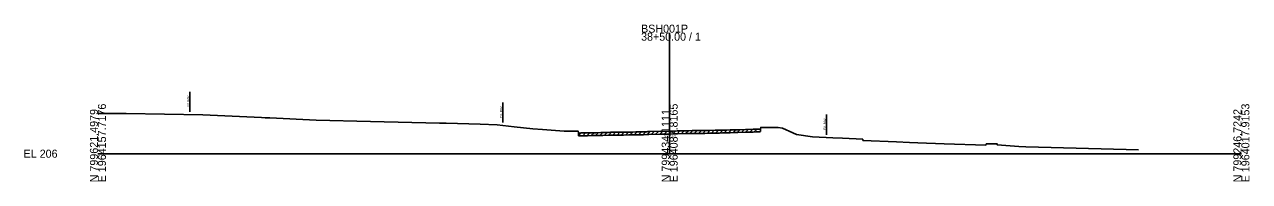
# Model space of a CAD drawing. Extents: x -26 to 1403, y -10 to 19587.
# Drawn here: x 974.3 to 1402.8, y 2490.3 to 2545.1 of the extents above; entities that cross this region are included whole.
import ezdxf

# ---------------------------------------------------------------- set-up
doc = ezdxf.new("R2010")
doc.units = 0
for name, color, linetype in [('Default', 7, 'Continuous'), ('RD_GPK_XS_Cell', 7, 'Continuous'), ('RD_XS_ExGround', 7, 'Continuous'), ('RD_XS_ExPaveRet', 7, 'Continuous'), ('RD_XS_ExRW', 7, 'Continuous'), ('RD_XS_TX_Elev_EX', 7, 'Continuous')]:
    doc.layers.add(name, color=color, linetype=linetype)

msp = doc.modelspace()

# ---------------------------------------------------------------- linework, layer by layer
at = {"layer": 'RD_GPK_XS_Cell'}
for p, q in [((1200, 2500), (1200, 2542.26)), ((1000, 2500), (1200, 2500)), ((1200, 2500), (1400, 2500))]:
    msp.add_line(p, q, dxfattribs=at)
at = {"layer": 'RD_XS_ExGround'}
msp.add_lwpolyline([(1000, 2514.09), (1009.85, 2513.98), (1036.73, 2513.55), (1057.27, 2512.59), (1058.5, 2512.54), (1060.15, 2512.47), (1076.38, 2511.69), (1095.34, 2511.2), (1119.51, 2510.7), (1121.79, 2510.64), (1133.7, 2510.27), (1139.68, 2510.06), (1145.66, 2509.4), (1152.08, 2508.65), (1155.46, 2508.44), (1163.14, 2507.88), (1166.11, 2507.88), (1167.98, 2507.87), (1168.08, 2507.27), (1168.12, 2507.19), (1168.94, 2507.24), (1169.69, 2507.25), (1170.57, 2507.26), (1171.29, 2507.28), (1173.23, 2507.31), (1174.12, 2507.33), (1175.89, 2507.38), (1176.57, 2507.4), (1178.56, 2507.45), (1179.29, 2507.47), (1180.89, 2507.51), (1181.29, 2507.51), (1183.87, 2507.52), (1185.76, 2507.55), (1186.53, 2507.56), (1188.22, 2507.58), (1189.2, 2507.59), (1190.81, 2507.64), (1191.97, 2507.68), (1192.36, 2507.71), (1192.77, 2507.73), (1196.92, 2507.83), (1197.61, 2507.84), (1199.09, 2507.85), (1200, 2507.87), (1201.33, 2507.91), (1202.57, 2507.94), (1205.46, 2508.01), (1206.65, 2508.03), (1207.91, 2508.05), (1209.11, 2508.06), (1210.59, 2508.08), (1211.05, 2508.08), (1212.31, 2508.1), (1213.24, 2508.12), (1213.79, 2508.13), (1215.89, 2508.17), (1217.47, 2508.2), (1218.51, 2508.23), (1219.42, 2508.26), (1221.21, 2508.32), (1222.25, 2508.35), (1223.88, 2508.39), (1226.56, 2508.48), (1229.2, 2508.57), (1230.21, 2508.6), (1230.73, 2508.61), (1231.48, 2508.59), (1231.74, 2508.71), (1231.84, 2509.16), (1233.22, 2509.17), (1236.84, 2509.2), (1237.92, 2509.11), (1239.5, 2508.97), (1243.07, 2507.28), (1244.32, 2506.65), (1249.95, 2505.89), (1257.03, 2505.53), (1260.5, 2505.44), (1267.53, 2505.06), (1267.63, 2504.61), (1279.3, 2504.11), (1283.94, 2503.88), (1286.85, 2503.81), (1296.03, 2503.48), (1310.65, 2502.99), (1310.75, 2503.44), (1312.13, 2503.49), (1314.52, 2503.49), (1314.62, 2503.04), (1322.13, 2502.56), (1324.63, 2502.45), (1333.48, 2502.18), (1364.05, 2501.34)], dxfattribs=at)
at = {"layer": 'RD_XS_ExPaveRet'}
for p, q in [((1168.08, 2506.39), (1168.08, 2507.39)), ((1168.08, 2506.39), (1168.93, 2507.24)), ((1169.58, 2506.25), (1170.59, 2507.26)), ((1171.08, 2506.27), (1172.1, 2507.29)), ((1172.58, 2506.3), (1173.6, 2507.32)), ((1174.08, 2506.33), (1175.11, 2507.36)), ((1175.58, 2506.37), (1176.61, 2507.4)), ((1177.08, 2506.41), (1178.11, 2507.44)), ((1178.58, 2506.45), (1179.61, 2507.48)), ((1180.08, 2506.49), (1181.1, 2507.51)), ((1181.58, 2506.51), (1182.58, 2507.52)), ((1183.08, 2506.52), (1184.08, 2507.52)), ((1184.58, 2506.53), (1185.59, 2507.54)), ((1186.08, 2506.55), (1187.09, 2507.56)), ((1187.58, 2506.57), (1188.59, 2507.58)), ((1189.08, 2506.59), (1190.11, 2507.62)), ((1190.58, 2506.63), (1191.61, 2507.67)), ((1192.08, 2506.69), (1193.13, 2507.74)), ((1193.58, 2506.75), (1194.61, 2507.78)), ((1195.08, 2506.79), (1196.11, 2507.81)), ((1196.58, 2506.83), (1197.59, 2507.84)), ((1198.08, 2506.84), (1199.09, 2507.85)), ((1199.58, 2506.86), (1200.6, 2507.89)), ((1201.08, 2506.9), (1202.11, 2507.93)), ((1201.33, 2506.91), (1202.57, 2506.94)), ((1202.57, 2506.94), (1205.46, 2507.01)), ((1202.58, 2506.94), (1203.61, 2507.97)), ((1204.08, 2506.98), (1205.11, 2508)), ((1205.46, 2507.01), (1206.65, 2507.03)), ((1205.58, 2507.02), (1206.59, 2508.03)), ((1206.65, 2507.03), (1207.91, 2507.05)), ((1207.08, 2507.04), (1208.09, 2508.05)), ((1207.91, 2507.05), (1209.11, 2507.06)), ((1208.58, 2507.06), (1209.59, 2508.07)), ((1209.11, 2507.06), (1210.59, 2507.08)), ((1210.08, 2507.07), (1211.09, 2508.08)), ((1210.59, 2507.08), (1211.05, 2507.08)), ((1211.05, 2507.08), (1212.31, 2507.1)), ((1211.58, 2507.09), (1212.59, 2508.11)), ((1212.31, 2507.1), (1213.24, 2507.12)), ((1213.08, 2507.11), (1214.1, 2508.13)), ((1213.24, 2507.12), (1213.79, 2507.13)), ((1213.79, 2507.13), (1215.89, 2507.17)), ((1214.58, 2507.14), (1215.6, 2508.16)), ((1215.89, 2507.17), (1217.47, 2507.2)), ((1216.08, 2507.17), (1217.1, 2508.2)), ((1217.47, 2507.2), (1218.51, 2507.23)), ((1217.58, 2507.21), (1218.6, 2508.23)), ((1218.51, 2507.23), (1219.42, 2507.26)), ((1219.08, 2507.25), (1220.11, 2508.28)), ((1219.42, 2507.26), (1221.21, 2507.32)), ((1220.58, 2507.3), (1221.61, 2508.33)), ((1221.21, 2507.32), (1222.25, 2507.35)), ((1222.08, 2507.34), (1223.11, 2508.37)), ((1222.25, 2507.35), (1223.88, 2507.39)), ((1223.58, 2507.39), (1224.61, 2508.42)), ((1223.88, 2507.39), (1226.56, 2507.48)), ((1225.08, 2507.43), (1226.11, 2508.46)), ((1226.56, 2507.48), (1229.2, 2507.57)), ((1226.58, 2507.48), (1227.62, 2508.51)), ((1228.08, 2507.53), (1229.12, 2508.57)), ((1229.2, 2507.57), (1230.21, 2507.6)), ((1229.58, 2507.58), (1230.6, 2508.6)), ((1230.21, 2507.6), (1230.73, 2507.61)), ((1230.73, 2507.61), (1231.48, 2507.59)), ((1231.48, 2507.59), (1231.74, 2507.71)), ((1231.74, 2508.71), (1231.74, 2507.71)), ((1168.08, 2506.39), (1168.12, 2506.19)), ((1168.12, 2506.19), (1168.94, 2506.24)), ((1168.94, 2506.24), (1169.69, 2506.25)), ((1169.69, 2506.25), (1170.57, 2506.26)), ((1170.57, 2506.26), (1171.29, 2506.28)), ((1171.29, 2506.28), (1173.23, 2506.31)), ((1173.23, 2506.31), (1174.12, 2506.33)), ((1174.12, 2506.33), (1175.89, 2506.38)), ((1175.89, 2506.38), (1176.57, 2506.4)), ((1176.57, 2506.4), (1178.56, 2506.45)), ((1178.56, 2506.45), (1179.29, 2506.47)), ((1179.29, 2506.47), (1180.89, 2506.51)), ((1180.89, 2506.51), (1181.29, 2506.51)), ((1181.29, 2506.51), (1183.87, 2506.52)), ((1183.87, 2506.52), (1185.76, 2506.55)), ((1185.76, 2506.55), (1186.53, 2506.56)), ((1186.53, 2506.56), (1188.22, 2506.58)), ((1188.22, 2506.58), (1189.2, 2506.59)), ((1189.2, 2506.59), (1190.81, 2506.64)), ((1190.81, 2506.64), (1191.97, 2506.68)), ((1191.97, 2506.68), (1192.36, 2506.71)), ((1192.36, 2506.71), (1192.77, 2506.73)), ((1192.77, 2506.73), (1196.92, 2506.83)), ((1196.92, 2506.83), (1197.61, 2506.84)), ((1197.61, 2506.84), (1199.09, 2506.85)), ((1199.09, 2506.85), (1200, 2506.87)), ((1200, 2506.87), (1201.33, 2506.91))]:
    msp.add_line(p, q, dxfattribs=at)
at = {"layer": 'RD_XS_ExRW'}
for p, q in [((1032.2, 2514.62), (1032.2, 2521.62)), ((1141.63, 2510.85), (1141.63, 2517.85)), ((1254.92, 2506.64), (1254.92, 2513.64))]:
    msp.add_line(p, q, dxfattribs=at)

# ---------------------------------------------------------------- texts
at = {"layer": 'Default'}
msp.add_text('-', height=0.0001, dxfattribs=at).set_placement((1000, 2500))
at = {"layer": 'RD_GPK_XS_Cell'}
for s, p in [('38+50.00 / 1', (1190, 2539.46)), ('BSH001P', (1190, 2542.26)), ('EL 206', (974, 2498.6))]:
    msp.add_text(s, height=2.8, dxfattribs=at).set_placement(p)
for s, p in [('E 1964157.7176', (1002.8, 2490)), ('E 1964087.8165', (1202.8, 2490)), ('E 1964017.9153', (1402.8, 2490)), ('N 799621.4979', (1000, 2490)), ('N 799434.1111', (1200, 2490)), ('N 799246.7242', (1400, 2490))]:
    msp.add_text(s, height=2.8, rotation=90, dxfattribs=at).set_placement(p)
at = {"layer": 'RD_XS_ExRW'}
for p in [(1031.95, 2516.29), (1141.38, 2512.52), (1254.67, 2508.31)]:
    msp.add_text('EX. R/W ', height=0.75, rotation=90, dxfattribs=at).set_placement(p)
at = {"layer": 'RD_XS_TX_Elev_EX'}
msp.add_text('213.87', height=1, dxfattribs=at).set_placement((1197.96, 2505.37))

doc.saveas('drawing.dxf')
